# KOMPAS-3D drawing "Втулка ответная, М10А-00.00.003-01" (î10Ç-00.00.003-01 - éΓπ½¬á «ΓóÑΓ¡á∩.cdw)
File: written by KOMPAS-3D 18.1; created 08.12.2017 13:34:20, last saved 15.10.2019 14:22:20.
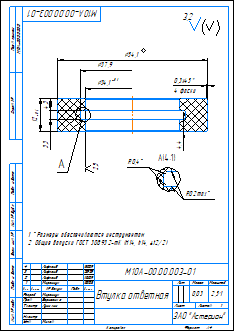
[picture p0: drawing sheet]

Sheet 1: A4, portrait

Document properties: Масса: 0.031838; Параметр неуказанной шероховатости: 3,2; Полное имя файла: ..\..\..\..\..\AquaProf\АкваProf 190\3Д модель\М10А-00.00.003 - Втулка ответная.m3d

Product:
- Part/product: Втулка ответная  | designation М10А-00.00.003-01
    Масса: 0.031838
    source file: М10А-00.00.003-01 - Втулка ответная.cdw
- Part/product: Втулка ответная  | designation М10А-00.00.003-01
    Масса: 0.0274435
    Раздел спецификации: Детали
    Форматы листов документа: А4

Title block, sheet 1: Наименование: Втулка ответная; designation: М10А-00.00.003-01; Масса: 0,03; scale: 2,5:1; Количество листов документа: 1; organisation: ЗАО "Астерион"; Форматы листов документа: A4; stored path: D:\АкваProf 190\Чертежи\М10А-00.00.003 - Втулка ответная.cdw; Разработал: Мирончук; Проверил: Борисенко; Т. контр.: Лучихин; Утвердил: Милов

Views: Вид 1, Слева, Проекционный вид 2, Местный разрез 1, Выносной элемент 3, Выносной элемент А, Выносной элемент
Referenced files in D:\АкваProf 190\3Д модель\: М10А-00.00.003 - Втулка ответная.m3d
Referenced files in D:\AquaProf\АкваProf 190\3Д модель\: М10А-00.00.003 - Втулка ответная.m3d
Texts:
  R0.2max*
  Лифлянд
Dimensions and other numbers on the sheet: 34,1; 12; 3,3; 37,9; 0,3; 4 фаски; 2,5; 4,4; 4,3; 54,1; 1; 0,4; 3,2; 2,5:1; 0,03; 10.01.2018; 2; 11.04.2019; 3; 23.09.2019; 4; 15.10.2019

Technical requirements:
  *Размеры обеспечиваются инструментом.
  Общие допуски ГОСТ 30893.2-mK (H14, h14,  t2/2).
